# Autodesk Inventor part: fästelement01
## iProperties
Created: 2001-12
Part Number: fästelement01
Material: Steel, Mild
Document SubType Name: Modeling
Designer: Tobben
Control State: 0
Master: False
Checked Out: False
Shininess: 64.0
Length Units: 11269
Angle Units: 11279
Time Units: 11290
Mass Units: 11283
Length Display Precision: 3
Angle Display Precision: 2
Density: 0.0
Volumn: 0.0
Area: 0.0
PropertySet Name: Model Information
Author: Tobben
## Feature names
1. Extrusion1
2. Extrusion2
3. Fillet1
4. Extrusion3
